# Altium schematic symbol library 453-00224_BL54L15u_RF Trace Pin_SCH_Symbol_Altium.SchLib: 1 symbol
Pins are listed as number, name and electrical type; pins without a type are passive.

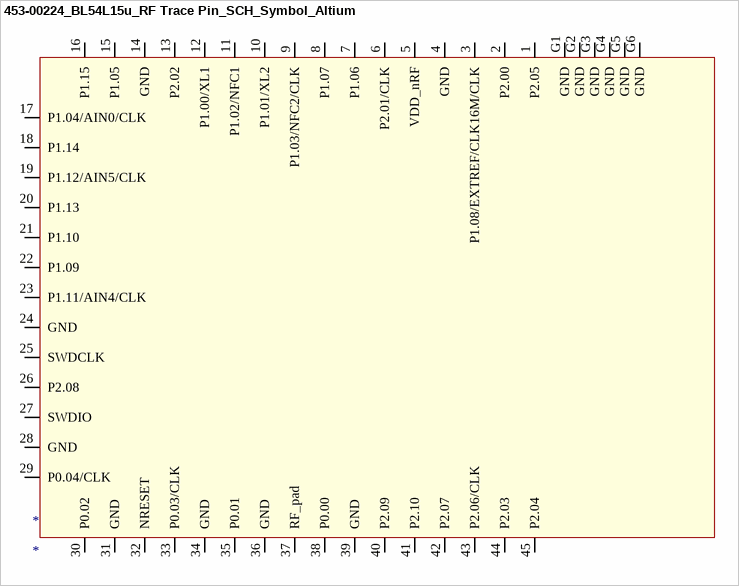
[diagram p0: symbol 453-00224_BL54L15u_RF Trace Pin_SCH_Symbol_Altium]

## 453-00224_BL54L15u_RF Trace Pin_SCH_Symbol_Altium
designator *
pins: 1 P2.05, 2 P2.00, 3 P1.08/EXTREF/CLK16M/CLK, 4 GND, 5 VDD_nRF, 6 P2.01/CLK, 7 P1.06, 8 P1.07, 9 P1.03/NFC2/CLK, 10 P1.01/XL2, 11 P1.02/NFC1, 12 P1.00/XL1, 13 P2.02, 14 GND, 15 P1.05, 16 P1.15, 17 P1.04/AIN0/CLK, 18 P1.14, 19 P1.12/AIN5/CLK, 20 P1.13, 21 P1.10, 22 P1.09, 23 P1.11/AIN4/CLK, 24 GND, 25 SWDCLK, 26 P2.08, 27 SWDIO, 28 GND, 29 P0.04/CLK, 30 P0.02, 31 GND, 32 NRESET, 33 P0.03/CLK, 34 GND, 35 P0.01, 36 GND, 37 RF_pad, 38 P0.00, 39 GND, 40 P2.09, 41 P2.10, 42 P2.07, 43 P2.06/CLK, 44 P2.03, 45 P2.04, G1 GND, G2 GND, G3 GND, G4 GND, G5 GND, G6 GND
